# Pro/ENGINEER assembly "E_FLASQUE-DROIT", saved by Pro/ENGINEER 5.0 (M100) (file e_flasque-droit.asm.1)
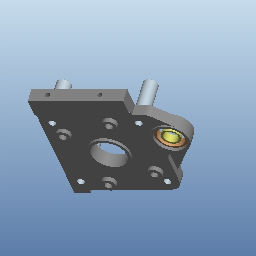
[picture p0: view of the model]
Units: millimeter Newton Second (mmNs); MM, TONNE, HOURS

Other components: 2-FLASQUE_DROIT, ROULEMENT-BC_10X22X6

Other named items: A-DROITE, A-DESSUS, A-FACE, A-R0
